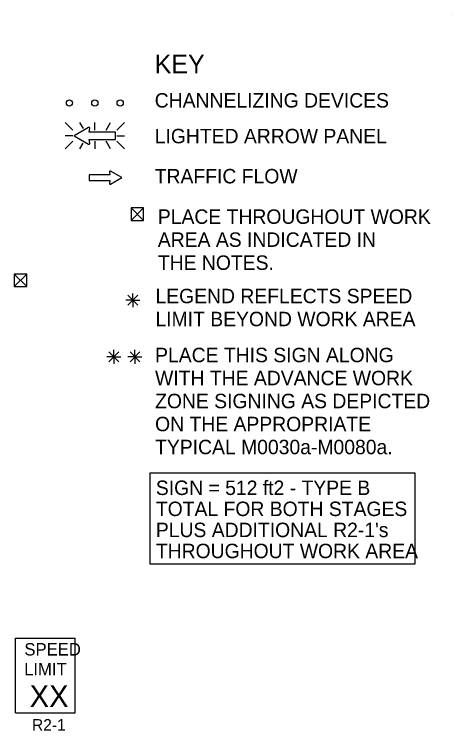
# Model space of a CAD drawing. Extents: x 16724 to 19508, y 5703 to 6974.
# Drawn here: x 17142.3 to 17423.5, y 6469.8 to 6930.8 of the extents above; entities that cross this region are included whole.
import ezdxf

# ---------------------------------------------------------------- set-up
doc = ezdxf.new("R2010")
doc.units = 0
for name, color, linetype in [('BORDER', 7, 'Continuous'), ('MT_SCRATCH_LEVEL_E', 7, 'Continuous'), ('TRAFFIC_SIGNS_PR', 7, 'Continuous'), ('TYPICAL_TEXT_DIMEN_EX', 7, 'Continuous'), ('TYPICAL_TEXT_DIMEN_PR', 7, 'Continuous')]:
    doc.layers.add(name, color=color, linetype=linetype)

msp = doc.modelspace()

# ---------------------------------------------------------------- linework, layer by layer
at = {"layer": 'BORDER'}
msp.add_line((17423.55, 6930.8), (17423.55, 6930.8), dxfattribs=at)
at = {"layer": 'MT_SCRATCH_LEVEL_E'}
for p, q in [((17203.77, 6827.55), (17190.52, 6827.55)), ((17190.52, 6827.55), (17190.52, 6823.81)), ((17203.46, 6829.33), (17203.77, 6827.55)), ((17211.38, 6825.7), (17204.14, 6829.81)), ((17190.52, 6823.81), (17203.77, 6823.81)), ((17203.77, 6823.81), (17203.46, 6822.03)), ((17204.14, 6821.55), (17211.38, 6825.7))]:
    msp.add_line(p, q, dxfattribs=at)
for centre, start, end in [((17203.92, 6829.4), 60.4248, 189.9638), ((17203.92, 6821.96), 170.0362, 299.7731)]:
    msp.add_arc(centre, 0.463, start, end, dxfattribs=at)
at = {"layer": 'TRAFFIC_SIGNS_PR'}
for p, q in [((17174.97, 6861.12), (17179.9, 6856.19)), ((17186.73, 6857.31), (17184.52, 6861.13)), ((17194.05, 6856.19), (17194.05, 6861.13)), ((17201.29, 6856.19), (17204.14, 6861.13)), ((17208.2, 6856.19), (17213.14, 6861.13)), ((17179.9, 6852.64), (17174.97, 6852.64)), ((17208.2, 6852.64), (17213.14, 6852.64)), ((17174.97, 6844.15), (17179.9, 6849.08)), ((17184.48, 6844.15), (17186.59, 6847.81)), ((17194.05, 6849.08), (17194.05, 6844.15)), ((17204.18, 6844.15), (17201.33, 6849.08)), ((17208.2, 6849.08), (17213.14, 6844.15)), ((17143.01, 6529.36), (17181.45, 6529.36)), ((17143.01, 6481.3), (17143.01, 6529.36)), ((17181.45, 6481.3), (17181.45, 6529.36)), ((17143.01, 6481.3), (17181.45, 6481.3))]:
    msp.add_line(p, q, dxfattribs=at)
for points in [[(17189.98, 6857.91), (17180.69, 6852.64), (17189.98, 6847.32)], [(17190.85, 6847.94), (17190.45, 6850.21), (17207.47, 6850.21), (17207.47, 6855.01), (17190.45, 6855.01), (17190.86, 6857.3)]]:
    msp.add_lwpolyline(points, dxfattribs=at)
for centre in [(17177.76, 6873.75), (17194.06, 6873.75), (17210.36, 6873.75)]:
    msp.add_circle(centre, 2, dxfattribs=at)
for centre, radius, start, end in [((17190.27, 6857.39), 0.598, 350.7308, 118.8916), ((17190.26, 6847.84), 0.597, 241.4833, 9.9593)]:
    msp.add_arc(centre, radius, start, end, dxfattribs=at)
at = {"layer": 'TYPICAL_TEXT_DIMEN_EX'}
msp.add_lwpolyline([(17229.59, 6635.73), (17399.96, 6635.73), (17399.96, 6576.99), (17229.59, 6576.99)], close=True, dxfattribs=at)
at = {"layer": 'TYPICAL_TEXT_DIMEN_PR'}
for p, q in [((17217.43, 6806.23), (17225.43, 6798.23)), ((17217.43, 6798.23), (17225.43, 6806.23)), ((17142.31, 6763.56), (17150.31, 6755.56)), ((17142.31, 6755.56), (17150.31, 6763.56)), ((17215.33, 6749.99), (17221.71, 6743.62)), ((17221.71, 6749.99), (17215.33, 6743.62)), ((17218.52, 6746.81), (17218.52, 6751.26)), ((17218.52, 6746.81), (17213.99, 6746.81)), ((17218.52, 6746.81), (17221.71, 6746.81)), ((17218.52, 6746.81), (17222.99, 6746.81)), ((17218.52, 6746.81), (17218.52, 6742.31)), ((17203.19, 6713.62), (17209.57, 6707.24)), ((17209.57, 6713.62), (17203.19, 6707.24)), ((17206.38, 6710.43), (17206.38, 6714.89)), ((17216.7, 6713.62), (17223.07, 6707.24)), ((17223.07, 6713.62), (17216.7, 6707.24)), ((17219.88, 6710.43), (17219.88, 6714.89)), ((17206.38, 6710.43), (17201.85, 6710.43)), ((17206.38, 6710.43), (17209.57, 6710.43)), ((17206.38, 6710.43), (17210.86, 6710.43)), ((17206.38, 6710.43), (17206.38, 6705.93)), ((17219.88, 6710.43), (17215.35, 6710.43)), ((17219.88, 6710.43), (17223.07, 6710.43)), ((17219.88, 6710.43), (17224.36, 6710.43)), ((17219.88, 6710.43), (17219.88, 6705.93))]:
    msp.add_line(p, q, dxfattribs=at)
for points in [[(17217.43, 6806.23), (17217.43, 6798.23), (17225.43, 6798.23), (17225.43, 6806.23)], [(17142.31, 6763.56), (17142.31, 6755.56), (17150.31, 6755.56), (17150.31, 6763.56)]]:
    msp.add_lwpolyline(points, close=True, dxfattribs=at)
msp.add_open_spline([(17311.46, 6747.39), (17311.48, 6747.39), (17311.49, 6747.39), (17311.49, 6747.39)], degree=2, dxfattribs=at)

# ---------------------------------------------------------------- texts
at = {"layer": 'TRAFFIC_SIGNS_PR'}
for s, height, p in [('SPEED', 8.01, (17148.78, 6518.21)), ('LIMIT', 8.01, (17148.62, 6505.39)), ('XX', 14.048, (17152.13, 6485.06)), ('R2-1', 7.449, (17153.7, 6469.85))]:
    msp.add_text(s, height=height, dxfattribs=at).set_placement(p)
at = {"layer": 'TYPICAL_TEXT_DIMEN_EX'}
for s, height, p in [('KEY', 12, (17232.6, 6892.86)), ('CHANNELIZING DEVICES', 9.3, (17232.6, 6870.81)), ('LIGHTED ARROW PANEL', 9.3, (17232.6, 6847.81)), ('TRAFFIC FLOW', 9.3, (17232.6, 6822.01)), ('PLACE THROUGHOUT WORK', 9.3, (17234.6, 6795.97)), ('AREA AS INDICATED IN', 9.3, (17234.6, 6781.17)), ('THE NOTES.', 9.3, (17234.6, 6766.37)), ('LEGEND REFLECTS SPEED', 9.3, (17233.07, 6744.9)), ('LIMIT BEYOND WORK AREA', 9.3, (17233.07, 6730.1)), ('PLACE THIS SIGN ALONG', 9.3, (17232.83, 6706.93)), ('WITH THE ADVANCE WORK', 9.3, (17232.83, 6692.13)), ('ZONE SIGNING AS DEPICTED', 9.3, (17232.83, 6677.33)), ('ON THE APPROPRIATE', 9.3, (17232.83, 6662.53)), ('TYPICAL M0030a-M0080a.', 9.3, (17232.83, 6647.73)), ('SIGN = 512 ft2 - TYPE B', 9.3, (17233.32, 6621.49)), ('TOTAL FOR BOTH STAGES', 9.3, (17233.32, 6607.94)), ("PLUS ADDITIONAL R2-1's", 9.3, (17233.32, 6594.39)), ('THROUGHOUT WORK AREA', 9.3, (17233.32, 6580.84))]:
    msp.add_text(s, height=height, dxfattribs=at).set_placement(p)

doc.saveas('drawing.dxf')
